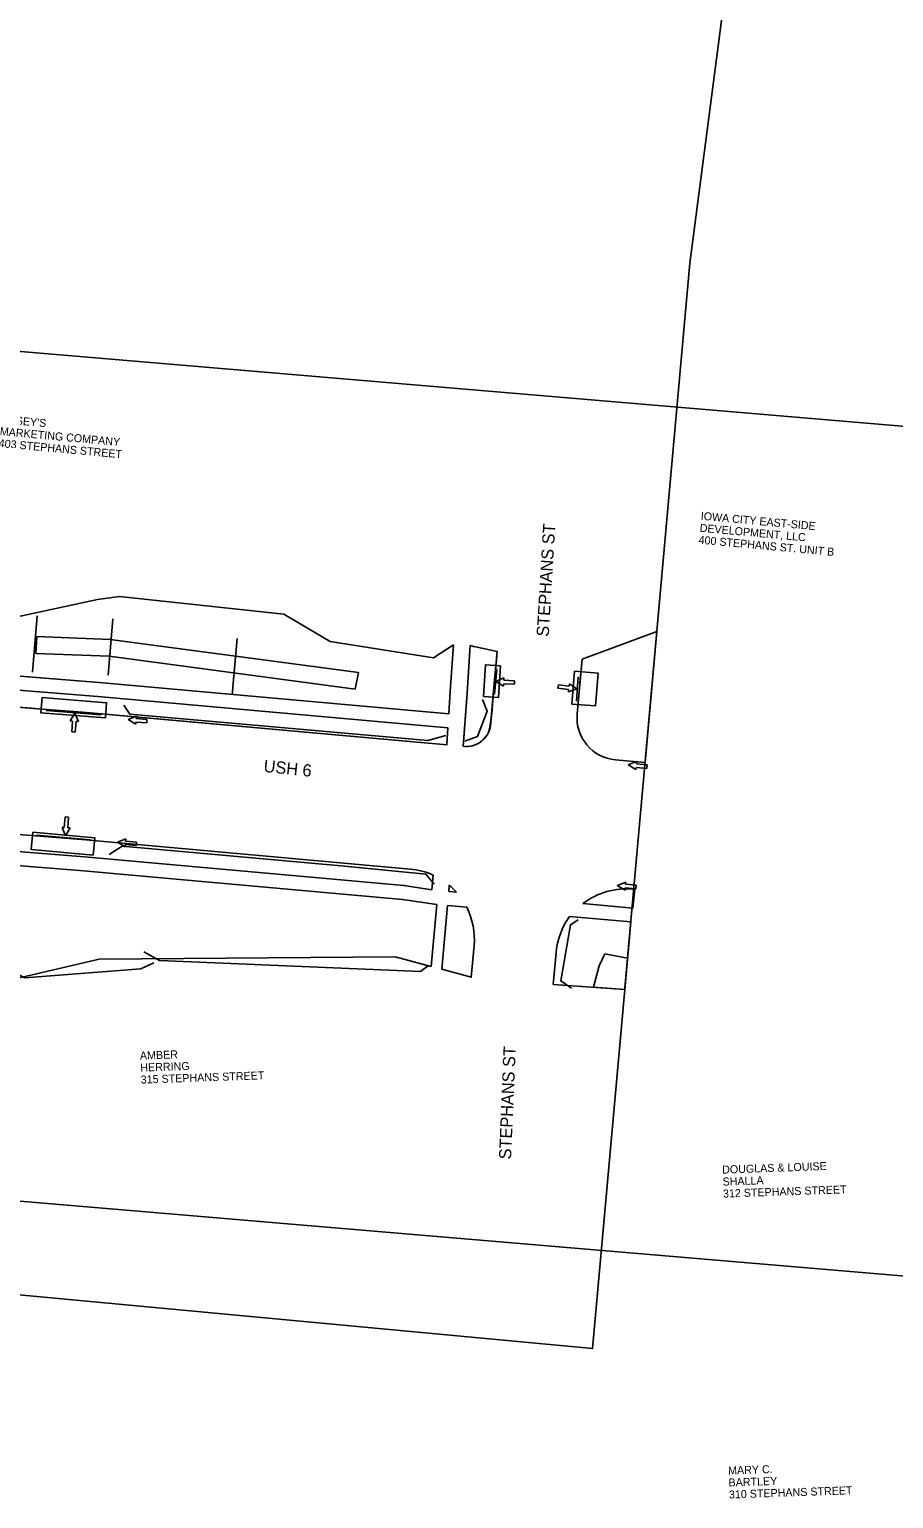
# Model space of a CAD drawing. Extents: x 20499351 to 20505779, y 7953198 to 7954637.
# Drawn here: x 20501580 to 20501886, y 7953653 to 7954174 of the extents above; entities that cross this region are included whole.
import ezdxf

# ---------------------------------------------------------------- set-up
doc = ezdxf.new("R2010")
doc.units = 0
for name, color, linetype in [('_CIVIL_CONSTRUCTION', 7, 'Continuous'), ('Contours Major', 7, 'Continuous'), ('Contours Minor', 7, 'Continuous'), ('Mulch', 7, 'Continuous'), ('NamedBoundary', 7, 'Continuous'), ('Terrain', 7, 'Continuous'), ('Terrains (working)', 7, 'Continuous'), ('TL_GroundIntercept', 7, 'Continuous')]:
    doc.layers.add(name, color=color, linetype=linetype)

msp = doc.modelspace()

# ---------------------------------------------------------------- linework, layer by layer
at = {"layer": '_CIVIL_CONSTRUCTION'}
for p, q in [((20501745.33, 7953942.88), (20501748.25, 7953944.17)), ((20501748.25, 7953944.17), (20501748.22, 7953943.38)), ((20501748.12, 7953941.31), (20501745.33, 7953942.88)), ((20501748.16, 7953942.11), (20501748.12, 7953941.31)), ((20501751.97, 7953941.93), (20501748.16, 7953942.11)), ((20501748.22, 7953943.38), (20501752.03, 7953943.2)), ((20501752.03, 7953943.2), (20501751.97, 7953941.93)), ((20501767.4, 7953940.51), (20501767.56, 7953941.77)), ((20501771.19, 7953940.04), (20501767.4, 7953940.51)), ((20501767.56, 7953941.77), (20501771.34, 7953941.3)), ((20501774.11, 7953940.32), (20501771.09, 7953939.25)), ((20501771.09, 7953939.25), (20501771.19, 7953940.04)), ((20501771.34, 7953941.3), (20501771.44, 7953942.09)), ((20501771.44, 7953942.09), (20501774.11, 7953940.32)), ((20501594.58, 7953928.99), (20501596.22, 7953931.73)), ((20501595.37, 7953928.93), (20501594.58, 7953928.99)), ((20501595.09, 7953925.12), (20501595.37, 7953928.93)), ((20501596.22, 7953931.73), (20501597.44, 7953928.77)), ((20501596.64, 7953928.83), (20501596.36, 7953925.03)), ((20501597.44, 7953928.77), (20501596.64, 7953928.83)), ((20501615.05, 7953929.43), (20501618.02, 7953930.61)), ((20501617.78, 7953927.76), (20501615.05, 7953929.43)), ((20501617.84, 7953928.55), (20501617.78, 7953927.76)), ((20501621.65, 7953928.23), (20501617.84, 7953928.55)), ((20501618.02, 7953930.61), (20501617.95, 7953929.82)), ((20501617.95, 7953929.82), (20501621.76, 7953929.49)), ((20501621.76, 7953929.49), (20501621.65, 7953928.23)), ((20501596.36, 7953925.03), (20501595.09, 7953925.12)), ((20501792.28, 7953913.45), (20501795.29, 7953914.56)), ((20501794.97, 7953911.72), (20501792.28, 7953913.45)), ((20501795.29, 7953914.56), (20501795.2, 7953913.77)), ((20501795.2, 7953913.77), (20501798.99, 7953913.35)), ((20501798.99, 7953913.35), (20501798.85, 7953912.09)), ((20501795.06, 7953912.51), (20501794.97, 7953911.72)), ((20501798.85, 7953912.09), (20501795.06, 7953912.51)), ((20501592.45, 7953891.2), (20501592.73, 7953895)), ((20501592.73, 7953895), (20501594, 7953894.91)), ((20501594, 7953894.91), (20501593.72, 7953891.11)), ((20501592.88, 7953888.3), (20501591.66, 7953891.25)), ((20501591.66, 7953891.25), (20501592.45, 7953891.2)), ((20501594.52, 7953891.05), (20501592.88, 7953888.3)), ((20501593.72, 7953891.11), (20501594.52, 7953891.05)), ((20501611.29, 7953886.01), (20501614.26, 7953887.18)), ((20501614.26, 7953887.18), (20501614.19, 7953886.39)), ((20501614.01, 7953884.33), (20501611.29, 7953886.01)), ((20501614.08, 7953885.13), (20501614.01, 7953884.33)), ((20501617.88, 7953884.79), (20501614.08, 7953885.13)), ((20501614.19, 7953886.39), (20501617.99, 7953886.05)), ((20501617.99, 7953886.05), (20501617.88, 7953884.79)), ((20501788.43, 7953870.69), (20501791.41, 7953871.87)), ((20501788.43, 7953870.69), (20501791.41, 7953871.87)), ((20501791.41, 7953871.87), (20501791.34, 7953871.08)), ((20501791.41, 7953871.87), (20501791.34, 7953871.08)), ((20501791.34, 7953871.08), (20501795.14, 7953870.75)), ((20501791.34, 7953871.08), (20501795.14, 7953870.75)), ((20501791.16, 7953869.02), (20501788.43, 7953870.69)), ((20501791.16, 7953869.02), (20501788.43, 7953870.69)), ((20501791.23, 7953869.81), (20501791.16, 7953869.02)), ((20501791.23, 7953869.81), (20501791.16, 7953869.02)), ((20501795.03, 7953869.49), (20501791.23, 7953869.81)), ((20501795.03, 7953869.49), (20501791.23, 7953869.81)), ((20501795.14, 7953870.75), (20501795.03, 7953869.49)), ((20501795.14, 7953870.75), (20501795.03, 7953869.49))]:
    msp.add_line(p, q, dxfattribs=at)
at = {"layer": 'Contours Major'}
for p, q in [((20501802.41, 7953960.63), (20501775.93, 7953950.79)), ((20501798.26, 7953914.21), (20501802.41, 7953960.63)), ((20501775.93, 7953950.79), (20501774.21, 7953931.42)), ((20501580.88, 7953933.45), (20501463.93, 7953942.74)), ((20501594.31, 7953932.38), (20501584.65, 7953933.15)), ((20501605.81, 7953931.47), (20501598.83, 7953932.02)), ((20501728.05, 7953920.5), (20501609.63, 7953931.1)), ((20501743.48, 7953927.61), (20501743.54, 7953928.31)), ((20501728.43, 7953926.49), (20501728.05, 7953920.5)), ((20501734.26, 7953919.95), (20501733.83, 7953919.98)), ((20501787.81, 7953915.15), (20501798.26, 7953914.21)), ((20501723.21, 7953874.31), (20501722.7, 7953869.06)), ((20501728.89, 7953870.71), (20501728.68, 7953868.53)), ((20501728.68, 7953868.53), (20501731.39, 7953868.28)), ((20501793.99, 7953862.67), (20501794.59, 7953869.36)), ((20501724.43, 7953863.89), (20501722.45, 7953841.98)), ((20501728.23, 7953863.55), (20501726.21, 7953840.95)), ((20501735.06, 7953862.94), (20501728.23, 7953863.55)), ((20501776.27, 7953864.26), (20501793.99, 7953862.67)), ((20501793.2, 7953857.73), (20501771.48, 7953859.67)), ((20501791.06, 7953833.84), (20501793.2, 7953857.73)), ((20501766.72, 7953846.76), (20501765.72, 7953835.6)), ((20501765.72, 7953835.6), (20501791.06, 7953833.84))]:
    msp.add_line(p, q, dxfattribs=at)
for points in [[(20501730.38, 7953955.92), (20501723.34, 7953951.36), (20501686.7, 7953957.09), (20501670.21, 7953966.82), (20501612.04, 7953973.01), (20501604.26, 7953971.98), (20501566.93, 7953963.96), (20501521.05, 7953966.17), (20501499.17, 7953992.95), (20501499.21, 7954013.01), (20501463.96, 7954015.91), (20501465.71, 7954009.45)], [(20501320.22, 7953991.82), (20501320.18, 7953991.82), (20501464.54, 7953948.71), (20501475.28, 7953945.85), (20501496.07, 7953944.2), (20501511.18, 7953945), (20501604.37, 7953937.6), (20501728.43, 7953926.49)], [(20501728.75, 7953931.48), (20501729.25, 7953939.35), (20501730.16, 7953952.73), (20501730.38, 7953955.92)], [(20501736.28, 7953955.63), (20501736.04, 7953952.15), (20501735.19, 7953938.78), (20501734.28, 7953926.16), (20501734.14, 7953924.25), (20501733.83, 7953919.98)], [(20501745.91, 7953953.5), (20501737.73, 7953955.3), (20501737.43, 7953955.38), (20501736.28, 7953955.63)], [(20501465.46, 7953953.65), (20501476.2, 7953950.79), (20501496.14, 7953949.21), (20501511.25, 7953950.02), (20501604.78, 7953942.58), (20501728.75, 7953931.48)], [(20501744.53, 7953938.8), (20501745.08, 7953944.78), (20501745.37, 7953947.76), (20501745.91, 7953953.5)], [(20501584.65, 7953933.15), (20501584.65, 7953933.13), (20501580.88, 7953933.43), (20501580.88, 7953933.45)], [(20501598.83, 7953932.02), (20501598.83, 7953932.1), (20501594.32, 7953932.46), (20501594.31, 7953932.38)], [(20501609.63, 7953931.1), (20501609.63, 7953931.1), (20501605.81, 7953931.44), (20501605.81, 7953931.47)], [(20501326.65, 7953908.51), (20501600.07, 7953886.78), (20501715.01, 7953876.49)], [(20501722.7, 7953869.06), (20501712.8, 7953870.66), (20501599.56, 7953880.8), (20501329.45, 7953902.27)], [(20501560.89, 7953878.86), (20501599.27, 7953875.81), (20501712.32, 7953865.69), (20501724.43, 7953863.89)], [(20501722.45, 7953841.98), (20501709.69, 7953845.42), (20501604.77, 7953844.53), (20501571.55, 7953836.74), (20501570.62, 7953840.47), (20501565.52, 7953860.92)], [(20501726.21, 7953840.95), (20501736.68, 7953838.13), (20501737.68, 7953849.36)]]:
    msp.add_lwpolyline(points, dxfattribs=at)
for centre, radius, start, end in [((20501789.15, 7953930.09), 15, 174.9256, 264.8834), ((20501712.78, 7953851.59), 25, 65.3451, 84.8834), ((20501712.78, 7953851.59), 25, 41.8993, 49.8891), ((20501791.88, 7953843.62), 25.88, 84.8834, 127.0915), ((20501712.78, 7953851.59), 25, 354.8834, 26.9932), ((20501792.96, 7953844.41), 26.35, 144.5948, 174.8834)]:
    msp.add_arc(centre, radius, start, end, dxfattribs=at)
msp.add_open_spline([(20501733.83, 7953919.98), (20501736.45, 7953919.69), (20501739.64, 7953920.92), (20501742.69, 7953923.97), (20501743.63, 7953926.8), (20501744.53, 7953938.8)], degree=3, dxfattribs=at)
at = {"layer": 'Contours Minor'}
for p, q in [((20501581.14, 7953946.26), (20501582.87, 7953966.19)), ((20501607.97, 7953945.19), (20501609.7, 7953965.11)), ((20501651.97, 7953938.2), (20501653.7, 7953958.12)), ((20501775.93, 7953950.79), (20501775.19, 7953942.5)), ((20501745.71, 7953947.19), (20501744.96, 7953938.4)), ((20501773.94, 7953935.98), (20501774.57, 7953944.62)), ((20501581.69, 7953933.38), (20501463.93, 7953942.74)), ((20501593.85, 7953932.42), (20501585.87, 7953933.05)), ((20501605.56, 7953931.14), (20501586.05, 7953932.63)), ((20501605.81, 7953931.47), (20501598.44, 7953932.05)), ((20501728.05, 7953920.5), (20501609.46, 7953931.12)), ((20501743.48, 7953927.61), (20501743.54, 7953928.31)), ((20501728.43, 7953926.49), (20501728.05, 7953920.5)), ((20501734.26, 7953919.95), (20501733.83, 7953919.98)), ((20501582.56, 7953888.44), (20501601.77, 7953886.84)), ((20501794.24, 7953869.39), (20501793.85, 7953869.43))]:
    msp.add_line(p, q, dxfattribs=at)
for points in [[(20501320.18, 7953991.82), (20501320.18, 7953991.82), (20501464.54, 7953948.71), (20501475.28, 7953945.85), (20501496.07, 7953944.2), (20501511.18, 7953945), (20501604.37, 7953937.6), (20501728.43, 7953926.49)], [(20501736.28, 7953955.63), (20501736.04, 7953952.15), (20501735.19, 7953938.78), (20501734.28, 7953926.16), (20501734.14, 7953924.25), (20501733.83, 7953919.98)], [(20501745.91, 7953953.5), (20501737.73, 7953955.3), (20501737.43, 7953955.38), (20501736.28, 7953955.63)], [(20501743.57, 7953928.3), (20501743.89, 7953931.43), (20501745.08, 7953944.78), (20501745.91, 7953953.5)], [(20501585.87, 7953933.05), (20501585.86, 7953933.01), (20501581.68, 7953933.35), (20501581.69, 7953933.38)], [(20501613.61, 7953934.54), (20501615.72, 7953931.34), (20501721.25, 7953921.99), (20501727.67, 7953923.82)], [(20501734.43, 7953921.8), (20501738.84, 7953923.49), (20501742.36, 7953932.4), (20501740.63, 7953936.53)], [(20501598.44, 7953932.05), (20501598.43, 7953932.03), (20501593.85, 7953932.4), (20501593.85, 7953932.42)], [(20501609.46, 7953931.12), (20501609.46, 7953931.1), (20501605.81, 7953931.43), (20501605.81, 7953931.47)], [(20501723.51, 7953871.07), (20501720.63, 7953874.69), (20501690.6, 7953877.57), (20501612.97, 7953884.57), (20501608.4, 7953881.58)], [(20501774.61, 7953858.53), (20501771.79, 7953856.71), (20501768.37, 7953836.84), (20501772.25, 7953834.25)], [(20501721.46, 7953842.13), (20501718.7, 7953840.23), (20501626.16, 7953844.08), (20501620.66, 7953847.2)], [(20501624.22, 7953843.19), (20501619.62, 7953841.11), (20501578.45, 7953837.98), (20501572.8, 7953840.81)]]:
    msp.add_lwpolyline(points, dxfattribs=at)
for points in [[(20501582.37, 7953952.83), (20501582.73, 7953958.82), (20501608.72, 7953957.85), (20501696.68, 7953946.12), (20501695.52, 7953940.24), (20501608.35, 7953951.86)], [(20501740.98, 7953937.57), (20501746.3, 7953937.23), (20501747.01, 7953948.51), (20501741.69, 7953948.84)], [(20501772.31, 7953934.93), (20501780.7, 7953934.27), (20501781.63, 7953945.91), (20501773.24, 7953946.57)], [(20501584.57, 7953937.21), (20501607.47, 7953935.38), (20501607.04, 7953930.04), (20501584.14, 7953931.86)], [(20501581.27, 7953889.53), (20501603.22, 7953887.57), (20501602.68, 7953881.43), (20501580.72, 7953883.39)]]:
    msp.add_lwpolyline(points, close=True, dxfattribs=at)
msp.add_open_spline([(20501733.83, 7953919.98), (20501736.17, 7953919.68), (20501739.64, 7953920.92), (20501741.63, 7953922.95), (20501743.52, 7953925.59), (20501743.57, 7953928.3)], degree=3, dxfattribs=at)
at = {"layer": 'Mulch'}
for p, q in [((20501802.41, 7953960.63), (20501775.93, 7953950.79)), ((20501798.26, 7953914.21), (20501802.41, 7953960.63)), ((20501775.93, 7953950.79), (20501774.21, 7953931.42)), ((20501787.81, 7953915.15), (20501798.26, 7953914.21))]:
    msp.add_line(p, q, dxfattribs=at)
for points in [[(20501521.63, 7953961.91), (20501521.48, 7953963), (20501521.4, 7953963.56), (20501521.24, 7953964.78), (20501521.05, 7953966.17), (20501566.93, 7953963.96), (20501604.26, 7953971.98), (20501612.04, 7953973.01), (20501670.21, 7953966.82), (20501686.7, 7953957.09), (20501723.34, 7953951.36), (20501730.38, 7953955.92)], [(20501728.75, 7953931.48), (20501604.78, 7953942.58), (20501523.71, 7953949.02), (20501523.17, 7953952.24), (20501522.86, 7953954.09), (20501522.52, 7953956.1)], [(20501730.38, 7953955.92), (20501730.16, 7953952.73), (20501729.25, 7953939.35), (20501728.75, 7953931.48)], [(20501743.57, 7953928.3), (20501743.89, 7953931.43), (20501745.08, 7953944.78), (20501745.91, 7953953.5), (20501737.73, 7953955.3), (20501737.43, 7953955.38), (20501736.28, 7953955.63), (20501736.04, 7953952.15), (20501735.19, 7953938.78), (20501733.83, 7953919.98)], [(20501463.93, 7953942.74), (20501581.69, 7953933.38), (20501581.68, 7953933.35), (20501585.86, 7953933.01), (20501585.87, 7953933.05), (20501593.85, 7953932.42), (20501593.85, 7953932.4), (20501598.43, 7953932.03), (20501598.44, 7953932.05), (20501605.81, 7953931.47), (20501605.81, 7953931.43), (20501609.46, 7953931.1), (20501609.46, 7953931.12), (20501728.05, 7953920.5), (20501728.43, 7953926.49), (20501604.37, 7953937.6), (20501511.18, 7953945)]]:
    msp.add_lwpolyline(points, dxfattribs=at)
msp.add_arc((20501789.15, 7953930.09), 15, 174.9256, 264.8834, dxfattribs=at)
msp.add_open_spline([(20501733.83, 7953919.98), (20501736.17, 7953919.68), (20501739.64, 7953920.92), (20501741.63, 7953922.95), (20501743.52, 7953925.59), (20501743.57, 7953928.3)], degree=3, dxfattribs=at)
at = {"layer": 'NamedBoundary'}
msp.add_lwpolyline([(20501161.33, 7954095.04), (20501136.01, 7953796.11), (20502073.14, 7953716.74), (20502098.46, 7954015.67)], close=True, dxfattribs=at)
at = {"layer": 'Terrain'}
msp.add_lwpolyline([(20501791.06, 7953833.84), (20501779.66, 7953706.56), (20499351.13, 7953933.78), (20499411.85, 7954636.65), (20501855.07, 7954405.25), (20501814.1, 7954091.19), (20501791.1, 7953834.34)], dxfattribs=at)
at = {"layer": 'Terrains (working)'}
msp.add_lwpolyline([(20501780.05, 7953834.6), (20501791.06, 7953833.84), (20501792.05, 7953844.92), (20501783.98, 7953846.41), (20501782.06, 7953842.15), (20501780.05, 7953834.6)], dxfattribs=at)

# ---------------------------------------------------------------- texts
at = {"layer": 'TL_GroundIntercept'}
for s, height, rotation, p in [('MARKETING COMPANY', 2.8346, 354.7645, (20501569.52, 7954030.24)), ("CASEY'S", 2.835, 354.7645, (20501569.91, 7954034.48)), ('403 STEPHANS STREET', 2.8346, 354.7645, (20501569.13, 7954026.01)), ('IOWA CITY EAST-SIDE', 2.8346, 354.7645, (20501817.91, 7954000.26)), ('STEPHANS ST', 4.32, 86.5716, (20501764.11, 7953958.73)), ('DEVELOPMENT, LLC', 2.8346, 354.7645, (20501817.53, 7953996.02)), ('400 STEPHANS ST. UNIT B', 2.8346, 354.7645, (20501817.14, 7953991.79)), ('USH 6', 4.32, 354.0545, (20501662.95, 7953910.92)), ('STEPHANS ST', 4.32, 87.6148, (20501750.79, 7953773.55)), ('AMBER', 2.835, 2.0248, (20501619.29, 7953808.95)), ('HERRING', 2.835, 2.0248, (20501619.44, 7953804.7)), ('315 STEPHANS STREET', 2.8346, 2.0248, (20501619.59, 7953800.45)), ('DOUGLAS & LOUISE', 2.8346, 2.0248, (20501825.63, 7953768.55)), ('SHALLA', 2.835, 2.0248, (20501825.78, 7953764.3)), ('312 STEPHANS STREET', 2.8346, 2.0248, (20501825.93, 7953760.05)), ('MARY C.', 2.835, 2.0248, (20501827.74, 7953661.93)), ('BARTLEY', 2.835, 2.0248, (20501827.89, 7953657.68)), ('310 STEPHANS STREET', 2.8346, 2.0248, (20501828.04, 7953653.43))]:
    msp.add_text(s, height=height, rotation=rotation, dxfattribs=at).set_placement(p)

doc.saveas('drawing.dxf')
